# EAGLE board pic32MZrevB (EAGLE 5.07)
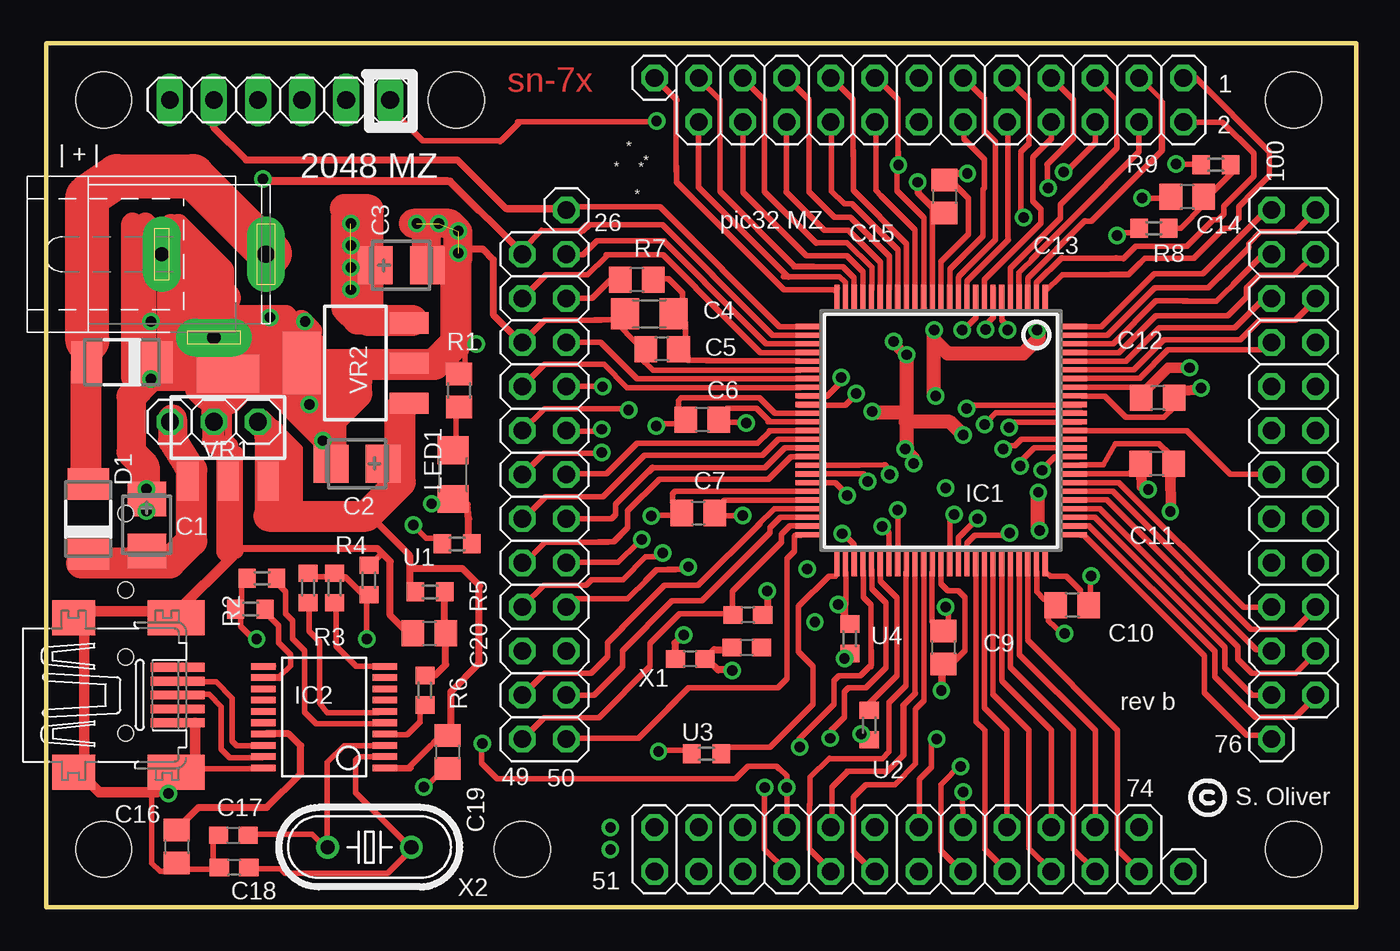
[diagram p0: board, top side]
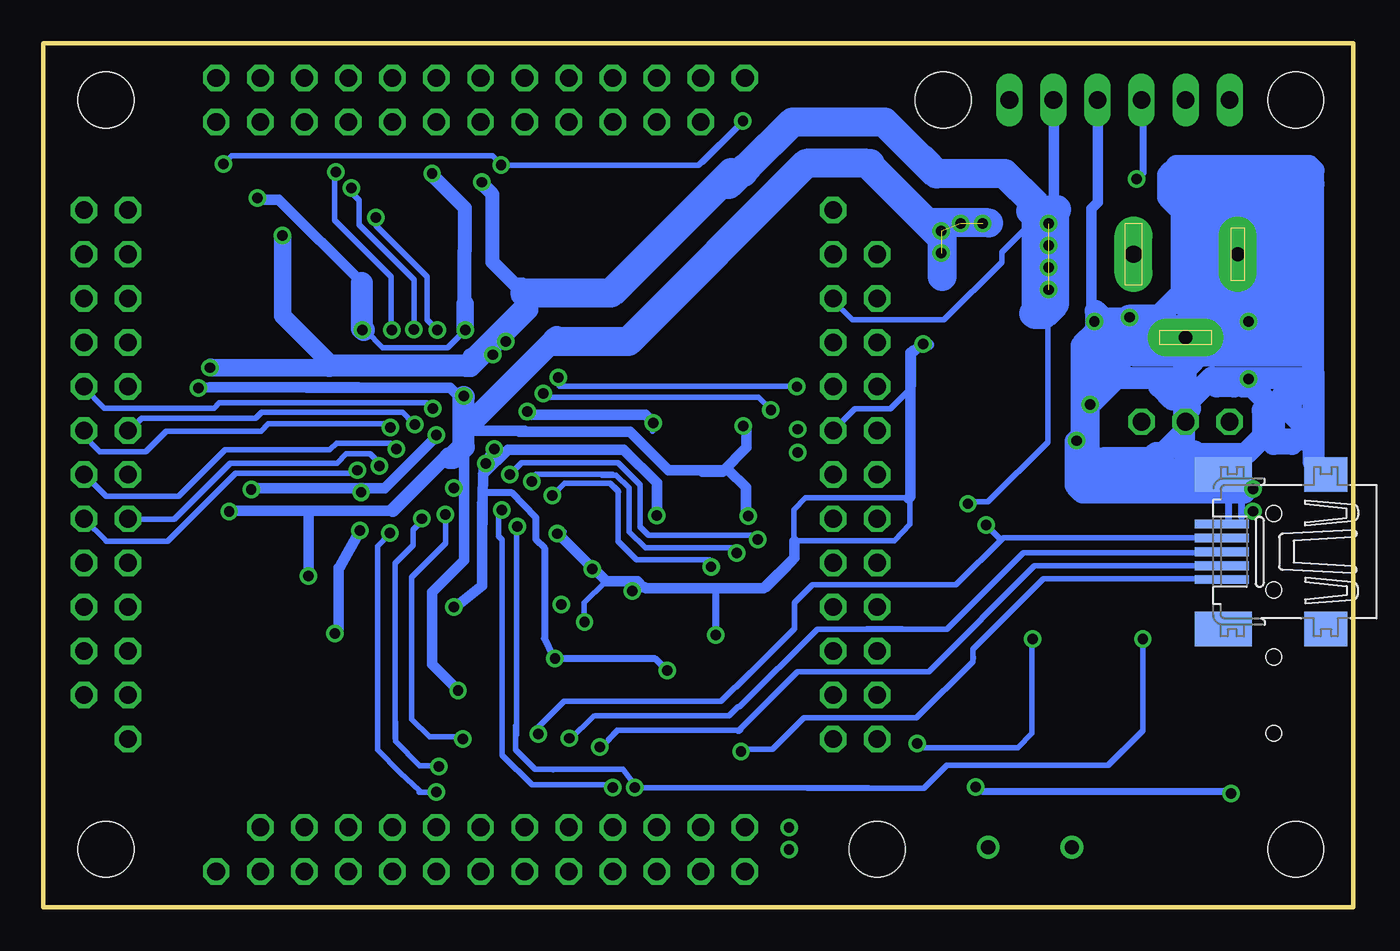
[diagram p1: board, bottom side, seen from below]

Size 75.5 x 49.78 mm. Coordinates in mm from the lower left corner, seen from the top.
Outline: 75.5,0.03 75.5,49.78 0,49.78 0,0.03
Outline: 75.5,0 0,0
Copper layers (1*16): Top 0.035mm / dielectric 1.5mm / Bottom 0.035mm
Design rules "default": minimum track width 10mil, minimum drill 24mil, track to track 8mil, track to pad 8mil, pad to pad 8mil, via to via 8mil, smd to smd 8mil, copper to edge 40mil, drill to drill 8mil, minimum pad ring 10mil, minimum via ring 8mil, stop-mask expansion 4mil, vias tented up to drill 0mil, thermal gap 10mil
Holes 3.2 mm at 3.31,46.52 3.31,3.34 71.89,3.34 71.89,46.52 23.63,46.52 27.44,3.34

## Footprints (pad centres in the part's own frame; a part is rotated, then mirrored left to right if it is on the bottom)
SPC4077 = drill 0.8 pad 2.184 long: 1 -3,0; 2 0,-4.8 | drill 1 pad 2.184 long: 3 3,0
C0805 = smd 1.3 x 1.5: 1 -0.95,0; 2 0.95,0
1X01 = drill 1.016 octagon: 1 0,0
2X12 = drill 1.016 octagon: 1 -13.97,-1.27; 2 -13.97,1.27; 3 -11.43,-1.27; 4 -11.43,1.27; 5 -8.89,-1.27; 6 -8.89,1.27; 7 -6.35,-1.27; 8 -6.35,1.27; 9 -3.81,-1.27; 10 -3.81,1.27; 11 -1.27,-1.27; 12 -1.27,1.27; 13 1.27,-1.27; 14 1.27,1.27; 15 3.81,-1.27; 16 3.81,1.27; 17 6.35,-1.27; 18 6.35,1.27; 19 8.89,-1.27; 20 8.89,1.27; 21 11.43,-1.27; 22 11.43,1.27; 23 13.97,-1.27; 24 13.97,1.27
R0603 = smd 1 x 1.1: 1 -0.85,0; 2 0.85,0
DO-214AC = smd 1.8 x 2.4: A 2.025,0; C -2.025,0
SOT223 = smd 1.219 x 2.235: 1 -2.311,-3.099; 2 0,-3.099; 3 2.311,-3.099 | smd 3.6 x 2.2: 4 0,3.099
CT3528 = smd 2 x 2.2: + -1.5,0; - 1.5,0
R0805 = smd 1.3 x 1.5: 1 -0.95,0; 2 0.95,0
C1206 = smd 1.6 x 1.8: 1 -1.4,0; 2 1.4,0
SQFP-S-14X14-100 = smd 0.3 x 1.6: 1 -6,-7.6; 2 -5.5,-7.6; 3 -5,-7.6; 4 -4.5,-7.6; 5 -4,-7.6; 6 -3.5,-7.6; 7 -3,-7.6; 8 -2.5,-7.6; 9 -2,-7.6; 10 -1.5,-7.6; 11 -1,-7.6; 12 -0.5,-7.6; 13 0,-7.6; 14 0.5,-7.6; 15 1,-7.6; 16 1.5,-7.6; 17 2,-7.6; 18 2.5,-7.6; 19 3,-7.6; 20 3.5,-7.6; 21 4,-7.6; 22 4.5,-7.6; 23 5,-7.6; 24 5.5,-7.6; 25 6,-7.6; 51 6,7.6; 52 5.5,7.6; 53 5,7.6; 54 4.5,7.6; 55 4,7.6; 56 3.5,7.6; 57 3,7.6; 58 2.5,7.6; 59 2,7.6; 60 1.5,7.6; 61 1,7.6; 62 0.5,7.6; 63 0,7.6; 64 -0.5,7.6; 65 -1,7.6; 66 -1.5,7.6; 67 -2,7.6; 68 -2.5,7.6; 69 -3,7.6; 70 -3.5,7.6; 71 -4,7.6; 72 -4.5,7.6; 73 -5,7.6; 74 -5.5,7.6; 75 -6,7.6 | smd 1.6 x 0.3: 26 7.6,-6; 27 7.6,-5.5; 28 7.6,-5; 29 7.6,-4.5; 30 7.6,-4; 31 7.6,-3.5; 32 7.6,-3; 33 7.6,-2.5; 34 7.6,-2; 35 7.6,-1.5; 36 7.6,-1; 37 7.6,-0.5; 38 7.6,0; 39 7.6,0.5; 40 7.6,1; 41 7.6,1.5; 42 7.6,2; 43 7.6,2.5; 44 7.6,3; 45 7.6,3.5; 46 7.6,4; 47 7.6,4.5; 48 7.6,5; 49 7.6,5.5; 50 7.6,6; 76 -7.6,6; 77 -7.6,5.5; 78 -7.6,5; 79 -7.6,4.5; 80 -7.6,4; 81 -7.6,3.5; 82 -7.6,3; 83 -7.6,2.5; 84 -7.6,2; 85 -7.6,1.5; 86 -7.6,1; 87 -7.6,0.5; 88 -7.6,0; 89 -7.6,-0.5; 90 -7.6,-1; 91 -7.6,-1.5; 92 -7.6,-2; 93 -7.6,-2.5; 94 -7.6,-3; 95 -7.6,-3.5; 96 -7.6,-4; 97 -7.6,-4.5; 98 -7.6,-5; 99 -7.6,-5.5; 100 -7.6,-6
C0603 = smd 1.1 x 1: 1 -0.85,0; 2 0.85,0
32005-201 = smd 3.1 x 0.5: 1 3,1.6; 2 3,0.8; 3 3,0; 4 3,-0.8; 5 3,-1.6 | smd 2.5 x 2: M1 -3,-4.45; M2 -3,4.45 | smd 3.3 x 2: M3 2.9,4.45; M4 2.9,-4.45 | hole 0.9: 0,2.2; 0,-2.2
SSOP20 = smd 0.38 x 1.4: 1 -2.925,-3.5; 2 -2.275,-3.5; 3 -1.625,-3.5; 4 -0.975,-3.5; 5 -0.325,-3.5; 6 0.325,-3.5; 7 0.975,-3.5; 8 1.625,-3.5; 9 2.275,-3.5; 10 2.925,-3.5; 11 2.925,3.5; 12 2.275,3.5; 13 1.625,3.5; 14 0.975,3.5; 15 0.325,3.5; 16 -0.325,3.5; 17 -0.975,3.5; 18 -1.625,3.5; 19 -2.275,3.5; 20 -2.925,3.5
HC49U-V = drill 0.813 round: 1 -2.413,0; 2 2.413,0
1X06 = drill 1.016 long: 1 -6.35,0; 2 -3.81,0; 3 -1.27,0; 4 1.27,0; 5 3.81,0; 6 6.35,0

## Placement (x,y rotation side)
E$1  [SPC4077]  9.66,37.63 0 top
E$2  [C0805]  64.07,29.35 180 top
E$3  [1X01]  29.98,40.17 0 top
E$4  [1X01]  35.06,47.79 0 top
E$5  [C0805]  51.77,40.97 270 top
E$6  [2X12]  51.57,46.52 0 top
E$7  [C0805]  64.02,25.57 180 top
E$8  [R0603]  63.84,39.13 180 top
E$9  [C0805]  65.77,40.94 180 top
E$10  [R0603]  67.42,42.79 0 top
E$11  [DO-214AC]  2.42,22.37 90 top
E$12  [SOT223]  17.81,31.36 90 top
E$13  [CT3528]  20.45,37 0 top
E$14  [R0805]  23.78,29.79 270 top
E$15  [C0805]  34.04,36.16 180 top
E$16  [C1206]  34.76,34.2 0 top
E$17  [C0805]  35.49,32.17 180 top
E$18  [C0805]  37.8,28.11 180 top
E$19  [SQFP-S-14X14-100]  51.57,27.47 180 top
E$20  [C0805]  59.14,17.42 180 top
E$21  [CT3528]  5.8,22.04 270 top
E$22  [SOT223]  10.47,27.65 0 top
E$23  [C0603]  37.11,14.32 180 top
E$24  [DO-214AC]  4.35,31.41 180 top
E$25  [R0603]  15.1,18.41 270 top
E$26  [R0603]  12.43,18.96 0 top
E$27  [CT3528]  17.91,25.57 180 top
E$28  [R0603]  22.13,18.18 0 top
E$29  [R0603]  23.68,20.95 0 top
E$30  [C1206]  23.45,24.93 90 top
E$31  [2X12]  28.71,23.66 90 top
E$32  [C0805]  37.57,22.72 0 top
E$33  [R0603]  47.43,10.51 90 top
E$34  [R0603]  16.62,18.41 270 top
E$35  [2X12]  71.89,26.2 90 top
E$36  [32005-201]  4.58,12.23 0 top
E$37  [SSOP20]  16.01,10.96 90 top
E$38  [R0603]  21.83,12.51 270 top
E$39  [C0805]  22.08,15.79 0 top
E$41  [R0603]  18.6,18.86 90 top
E$42  [R0603]  11.77,17.19 0 top
E$43  [C0603]  40.44,16.86 180 top
E$44  [C0603]  40.38,14.98 0 top
E$45  [C0805]  51.72,14.98 90 top
E$47  [1X01]  70.62,9.69 0 top
E$48  [C0805]  7.53,3.5 270 top
E$49  [C0603]  10.78,4.16 0 top
E$50  [C0603]  10.83,2.3 180 top
E$51  [HC49U-V]  18.63,3.47 180 top
E$52  [2X12]  49.03,3.34 0 top
E$53  [1X01]  65.54,2.07 0 top
E$55  [1X01]  7.12,27.98 0 top
E$56  [1X01]  9.66,27.98 0 top
E$57  [R0603]  38.06,8.86 180 top
E$58  [R0603]  46.31,15.49 270 top
E$59  [1X01]  12.2,27.98 0 top
E$100  [32005-201]  4.58,20.49 180 bottom
E$400  [C0805]  23.12,8.96 270 top
ICSP  [1X06]  13.47,46.52 0 top

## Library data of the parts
E$1 = con-jack
E$2 E$5 E$7-E$10 E$12-E$23 E$25-E$30 E$32-E$34 E$38 E$39 E$41-E$45 E$48-E$50 E$57 E$58 E$400 = smd-ipc
E$3 E$4 E$6 E$31 E$35 E$47 E$52 E$53 E$55 E$56 E$59 ICSP = pinhead
E$11 E$24 = diode
E$36 E$100 = con-cypressindustries
E$37 = cypress
E$51 = crystal

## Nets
S$5: E$6.16
S$22: E$52.7
S$51: E$31.15
S$61: E$35.11
S$101: E$31.4
S$259: E$6.18
S$283: E$31.2
S$476: E$52.8
S$520: E$35.9

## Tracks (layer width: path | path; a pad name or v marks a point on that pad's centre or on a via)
S$1  (via drill 0.6)
  other vias: 45.88,21.53 43.85,19.5 24.8,32.45 44.31,16.45 36.74,15.69 39.53,13.66 41.56,18.23
S$2
  Top 0.305: 50.58,35.5 50.58,39.74 49.03,41.29 49.03,42.84
S$3
  Top 0.305: 19.46,13.89 17.86,13.89 16.7,15.05 16.7,17.08
S$4
  Bottom 0.61: 51.32,29 51.47,28.85
S$5
  Top 0.305: E$6.16 56.62,46.55 56.62,43.96
S$6
  Top 0.305: 56.78,37.33 58.94,39.49 59.19,39.74 62.98,43.53 62.98,45.15
S$7  (via drill 0.6)
  other vias: 48.19,21.94
S$8
  Top 0.254: 60.44,47.79 61.68,46.55 61.68,44.01
S$9
  Top 0.305: 51.09,35.5 51.09,40.53
S$10  (via drill 0.6)
  other vias: 49.08,22.9
S$11
  Top 0.254: 62.98,45.23 63,45.2
S$12
  Bottom 0.305: 32.52,19.6 33.79,18.33 34.7,18.33 37.6,18.33
  Bottom 0.406: 43.87,19.73 43.16,18.76 41.23,18.76 40.8,18.33 34.7,18.33
S$13
  Top 0.254: 63,47.84 64.25,46.6 64.25,43.53
S$14
  Top 0.305: 27.46,17.34 28.68,18.56 31.1,18.56 31.43,18.89 33.23,18.89 34.55,20.21 35.24,20.21
S$15
  Top 0.305: 50.07,19.29 50.07,12.31 49.39,11.62 49.39,8.75 48.4,7.76
S$16
  Top 0.305: 56.88,40.68 57.34,40.23 57.34,39.41 54.09,36.16 54.09,35.73
S$17
  Bottom 0.305: 65.13,42.84 64.65,43.32 49.61,43.32 49.13,42.84
S$18
  Top 0.305: 34.68,18.94 33.51,17.77 30.51,17.77 30.03,17.29
S$19
  Top 0.305: 59.65,24.48 61.83,24.48 69.02,17.29 70.57,17.29 70.59,17.26
S$20
  Top 0.305: 51.57,35.6 51.57,37.2 53.15,38.78 53.15,40.86 52.41,41.6
S$21
  Top 0.305: 55.56,36.39 55.56,36.82 58.45,39.72 58.45,40.48 61.7,43.73 61.7,44.29
S$22
  Top 0.305: 42.68,2.05 E$52.7 41.41,3.34 41.41,6.9
S$23
  Top 0.406: 50.25,41.77 50.25,41.16 51.21,40.2
S$24
  Top 0.406: 52.18,42.31 53.17,42.31
S$25
  Top 0.305: 47.81,45.2 47.81,41.32 48.12,41.01 48.93,40.2 50.07,39.06 50.07,35.63
S$26
  Top 0.254: 60.48,45.23 60.46,45.25
S$27
  Top 0.305: 55.35,2.1 54.19,3.27
S$28
  Top 0.305: 41.13,22.11 37.58,18.56 35.64,18.56 33.13,16.04
S$29
  Bottom 0.61: 50.2,23.28 50.2,18.53 51.9,17.19
S$30
  Top 0.305: 51.06,19.32 51.06,16.48 51.14,16.4
S$31
  Top 0.305: 34.53,18.81 35.16,19.45 36.25,19.45
S$32
  Top 0.305: 52.08,35.68 52.08,36.77 53.98,38.67 53.98,41.37 54.06,41.44 54.06,43.12 52.89,44.29 52.89,45.23
S$33
  Top 0.305: 43.44,22.98 41.97,22.98 41.03,22.04
S$34
  Top 0.305: 48.57,19.37 48.57,21.58 48.22,21.94
S$35
  Bottom 0.305: 55.2,10.66 55.2,9.57 53.8,8.17 52.81,8.17 52.74,8.09
S$36  (via drill 0.6)
  other vias: 51.85,17.31
S$37
  Top 0.305: 43.42,22.47 42.32,22.47 41.72,21.86 41.72,21.58 37.8,17.67 36.08,17.67 33.23,14.83
S$39
  Bottom 0.406: 46.08,14.54 45.8,14.27
S$40
  Bottom 0.305: 35.47,9.03 35.39,9.11 33.48,9.11 31.66,10.94 25.33,10.94
S$41
  Top 1.778: 2.29,24.93 2.29,30.78
S$42
  Top 0.305: 51.57,19.35 51.57,18.66 51.98,18.25 52.56,18.25 52.94,17.87 52.94,14.8 52.13,13.99
S$43
  Top 0.305: 52,17.21 52,16.42 51.98,16.4
S$44  (via drill 0.6)
  other vias: 52.84,6.65
S$45
  Bottom 0.305: 32.06,30.04 45.75,30.04
S$46
  Top 0.305: 51.67,12.54 51.67,13.56 51.7,13.58
S$47
  Top 0.305: 59.6,17.95 59.6,18.28 58.81,19.07 57.87,19.07 57.64,19.29
S$48
  Top 0.813: 57.16,21.89 57.16,23.92
S$49
  Top 0.305: 60.18,19.22 60.18,18
S$50
  Top 0.305: 52.08,19.32 52.08,22.34 52.36,22.62
S$51
  Bottom 0.305: E$31.15 28.71,28.74 26.68,28.74 25.36,30.06 25.36,31.92 24.95,32.32 24.44,32.32
S$52
  Top 0.305: 45.14,8.6 44.03,7.48 44.03,5.91 43.98,5.86 | 45.22,2.1 43.98,3.34 43.98,5.86 | 43.98,5.86 43.98,5.91
S$53  (via drill 0.6)
  other vias: 52.71,8.12
S$54
  Top 0.406: 41.56,17.14 41.59,17.16 41.59,18.25
S$55
  Top 0.305: 59.72,30.98 62.7,30.98 64.42,32.71 68.82,32.71 69.93,33.82 71.99,33.82 73.21,35.04
S$56
  Top 0.305: 57.08,35.98 58.53,37.43
S$57
  Top 1.778: 8.39,25.19 8.39,21.12 7.12,19.85 2.04,19.85
S$58
  Top 0.305: 56.57,35.6 56.57,36.26 59.88,39.56
S$59
  Bottom 0.61: 51.42,29.3 52.05,29.94 60.31,29.94
S$60
  Top 0.305: 59.72,29.45 61.02,29.45 62.24,28.24 64.42,28.24 65.01,28.82
S$61
  Bottom 0.305: 55.25,26.48 55.51,26.74 58.61,26.74 58.99,26.36 65.03,26.36 67.7,23.69 71.86,23.69 73.11,24.93 E$35.11
S$62
  Top 0.305: 59.75,30.5 63.02,30.5 64.65,32.12 70.21,32.12 70.64,32.55
S$63
  Top 2.54: 12.89,37.69 8.44,42.13 4.07,42.13 2.37,40.94 2.37,32.66
S$64
  Top 2.54: 6.92,37.69 9.1,35.5 9.1,32.73
S$65
  Top 1.27: 13.06,27.47 13.06,22.93
S$66
  Bottom 0.305: 35.24,45.25 37.73,42.77 49.11,42.77
S$67
  Top 1.778: 12.84,22.55 18.45,22.55 20.4,24.5 20.4,28.69 20.48,28.77
S$68
  Top 1.778: 16.34,28.62 16.42,28.69 16.42,26.38
S$69
  Top 1.676: 7.27,28.13 7.27,26.89 8.14,25.52
S$70
  Top 1.778: 21.09,33.82 18.55,33.82 18.55,40.17
S$71  (via drill 0.6)
  other vias: 12.48,41.98
S$72
  Top 0.305: 58.76,33.47 60.82,33.47 63.86,36.52 66.66,36.52 70.29,40.15
S$73
  Top 0.305: 57.84,17.82 57.77,16.5 58.61,15.74 58.61,15.71
S$74
  Top 0.305: 59.75,27.47 65.74,27.47 68.26,24.96 70.54,24.96
S$75
  Top 0.305: 59.75,31.46 62.24,31.46 64.17,33.39 68.51,33.39 70.26,35.14
S$76
  Top 0.305: 57.09,19.35 57.09,18.18 57.49,17.75
S$77
  Top 0.305: 59.7,31.97 61.83,31.97 63.97,34.1 68.11,34.1 69.17,35.17 69.17,35.68 69.91,36.41 71.92,36.41 73.14,37.63
S$78
  Top 0.305: 59.75,32.48 61.5,32.48 63.97,34.94 65.74,34.94
S$79
  Top 0.305: 59.67,23.97 61.48,23.97 69.43,16.02 71.97,16.02 73.24,17.29
S$80
  Top 0.305: 59.62,29.96 62.44,29.96
S$81
  Top 0.305: 51.01,9.64 51.01,8.07 50.33,7.38 50.33,4.72
S$82  (via drill 0.6)
  Top 0.813: v52.84,27.22 52.08,27.98 49.54,27.98
S$83
  Top 0.305: 59.65,23.49 61.12,23.49 69.76,14.85 70.64,14.85 70.72,14.77
S$84
  Top 0.305: 59.65,22.98 60.74,22.98 68.69,15.03 68.69,14.29 69.48,13.5 72.02,13.5 73.29,14.77
S$85
  Bottom 0.305: 53.2,28.87 53.4,29.07 65.36,29.07 65.67,28.77 71.99,28.77 73.19,29.96
S$86
  Top 0.305: 65.54,34.92 67.44,34.92 68.84,36.31
S$87
  Top 0.305: 70.19,40.2 70.64,40.2
S$88
  Bottom 0.305: 49.26,22.72 49.26,21.38 49.05,21.17 49.05,8.78 47.33,7.05 42.96,7.05 42.88,6.98
S$89
  Bottom 1.016: 61.7,38.67 61.7,34.08 59.06,31.44
S$90
  Top 0.305: 73.21,40.15 71.99,38.93 69.98,38.93 69.3,38.24 69.3,38.02 67.57,36.29
S$91
  Bottom 0.61: 52.79,27.2 55.84,24.15 63.64,24.15 63.66,24.15
S$92
  Bottom 0.305: 33.56,28.69 34.27,29.4 42.81,29.4 45.09,29.4 46.52,29.4 46.69,29.58
S$93
  Top 0.305: 65.49,45.25 67.8,45.25 69.6,43.45 69.6,42.13 67.88,40.4 67.88,39.95 67.55,39.62 67.27,39.62 65.74,38.09 62.8,38.09 62.09,37.38
S$94
  Bottom 0.61: 57.36,29.96 65.9,29.96 66.38,29.94
S$95
  Top 0.305: 61.35,36.49 62.42,36.49 63.33,37.41 66.15,37.41 67.88,39.13 68.21,39.13 68.74,39.67 68.74,40.38 69.25,40.88
S$96
  Top 0.305: 59.75,24.98 62.42,24.98 62.59,25.16
S$97
  Top 0.305: 64.73,26.15 64.19,26.69
S$98  (via drill 0.6)
  other vias: 51.32,9.69
S$99
  Top 0.305: 49.11,43.5 49.11,42.84
S$100
  Top 0.61: 65.31,25.31 64.8,24.88 64.83,23.08
S$101
  Top 0.305: 33.23,16.17 33.23,16.15 32.34,15.26 32.34,14.44 31.4,13.5 28.71,13.5 E$31.4
S$102
  Top 0.305: 59.7,22.47 60.44,22.47 67.93,14.98 67.93,13.81 69.5,12.23 70.57,12.23 70.62,12.18
S$103
  Top 0.305: 59.72,21.99 60.1,21.99 67.34,14.75 67.34,13.3 69.68,10.96 71.99,10.96 73.26,12.23
S$104
  Top 0.305: 43.42,24.48 45.47,24.48 46.19,23.77
S$105
  Top 0.305: 43.42,24.98 47.1,24.98 47.38,24.7
S$106
  Top 0.305: 43.42,25.47 46.85,25.47 48.37,25.49
S$107
  Bottom 0.61: 55.3,22.85 64.68,22.85
S$108
  Top 0.305: 59.62,21.45 59.8,21.45 66.76,14.5 66.76,12.36 69.2,9.92 70.64,9.92 70.67,9.9
S$109
  Top 0.305: 30,19.88 32.95,19.88 34.09,21.02 34.09,21.05
S$110
  Bottom 0.406: 39.53,13.63 40.22,14.32 46.03,14.32
S$111
  Top 0.305: 43.39,23.46 39.1,23.46 38.95,23.31
S$112
  Top 0.305: 27.44,19.73 28.76,21.05 32.37,21.05
S$113
  Top 0.305: 34.93,25.37 32.8,23.23 32.8,22.62 32.57,22.39 29.93,22.39
S$114
  Top 0.305: 41.26,26.05 34.48,26.05 32.09,23.66 28.79,23.66 27.46,22.34
S$115
  Top 0.305: 29.93,24.98 32.29,24.98 34.04,26.74 41,26.74 41.74,27.47
S$116
  Top 0.305: 43.42,26.97 43.39,26.97 42.2,26.97 41.28,26.05
S$117
  Top 0.305: 32.16,26.18 28.68,26.18 27.41,24.91
S$118
  Top 0.305: 53.7,46.98 54.06,46.63 54.06,44.62
S$119  (via drill 0.6)
  other vias: 40.14,22.57
S$120
  Top 0.305: 59.65,25.52 60.92,25.52 61.63,26.71 64.12,26.71 64.78,26.05
S$121  (via drill 0.6)
  other vias: 40.34,27.91
S$122
  Top 0.305: 43.52,21.99 42.86,21.99 42.38,21.5 42.38,21.05 39.56,18.23 39.56,16.83 39.53,16.81 39.56,16.81
S$123  (via drill 0.6)
  other vias: 34.88,22.55
S$124
  Top 0.305: 39.48,14.93 39.53,14.88
S$125
  Top 0.305: 33.51,15.08 33.21,14.77 33.21,13.86 31.58,12.23 30.08,12.23
S$126  (via drill 0.6)
  other vias: 35.54,20.41 35.29,8.98 43.42,9.24 45.19,9.74 46.97,10
S$127
  Top 0.305: 41.69,27.47 43.37,27.47
S$128
  Top 0.305: 35.16,27.86 36.41,27.86
S$129  (via drill 0.6)
  other vias: 18.47,15.46
S$130
  Top 0.61: 63.51,24.15 63.15,24.22 63.13,25.01
S$131
  Top 0.61: 66,31.08 64.68,31.08 63.33,29.73 63.28,29.73 63.25,29.76
S$132  (via drill 0.6)
  other vias: 46.16,23.74
S$133
  Top 0.305: 41.72,27.98 41.59,27.98 | 41.72,27.98 43.39,27.98 | 41.72,27.98 40.93,28.77 39.23,28.77
S$134  (via drill 0.6)
  other vias: 48.62,24.93
S$135  (via drill 0.6)
  other vias: 47.35,24.53
S$136
  Top 0.305: 44.18,13 44.18,11.7 41.72,9.24 39.2,9.24
S$137
  Bottom 0.813: 51.21,34.64 51.21,37.89 51.21,37.94 51.21,40.3 53.07,42.16
S$138
  Top 0.305: 45.24,10.25 45.24,9.64 45.3,9.59
S$139
  Top 0.305: 68.16,36.85 68.13,36.85 66.99,35.7 63.89,35.7 63.84,35.65 63.71,35.53 61.15,32.96 59.7,32.96
S$140
  Bottom 1.016: 57.74,31.11 65.84,31.11 65.87,31.13
S$141  (via drill 0.6)
  other vias: 51.6,12.49 57.18,23.92 58.71,15.79 60.23,19.09 51.85,24.17
S$142
  Top 0.305: 68.41,35.91 70.14,37.63
S$143
  Top 0.305: 46.19,7.81 45.3,6.92 45.3,4.72 45.24,4.67
S$144  (via drill 0.6)
  other vias: 55.53,21.58
S$145  (via drill 0.6)
  other vias: 52.33,22.65
S$146  (via drill 0.6)
  other vias: 53.68,22.39
S$147  (via drill 0.6)
  other vias: 57.26,21.71
S$148
  Bottom 0.305: 35.31,10.2 41.46,10.2 42.38,10.2 | 42.38,10.2 42.43,10.2 42.93,9.69 | 42.38,10.2 43.37,9.21
S$149
  Bottom 0.813: 47.89,35.88 48.32,35.88 49.61,37.18 49.61,41.09 50.27,41.75
S$150
  Bottom 0.61: 60.21,22.65 60.21,19.35
S$151
  Top 0.305: 39.2,27.58 39.17,27.6 39.2,27.6
S$152
  Top 0.305: 39.28,28.72 39.25,28.69
S$153
  Top 0.305: 39.2,27.96 40.37,27.96
S$154
  Top 0.305: 43.39,28.46 41.99,28.46 41.1,29.35 36.58,29.35 36.43,29.2 36.43,28.59 36.41,28.57
S$155
  Top 0.305: 35.09,27.83 35.06,27.83
S$156
  Top 0.305: 43.42,25.97 42.93,25.97 41.64,24.68 35.34,24.68 33.51,22.85 33.51,21.89 32.7,21.07
S$157
  Top 1.778: 9.96,35.12 10.32,35.12
S$158
  Top 0.305: 43.42,26.48 42.58,26.48 41.44,25.34 34.96,25.34 34.73,25.11
S$159
  Top 0.305: 31.82,21.06 32.71,21.06 33.09,21.44
S$160
  Top 0.305: 43.42,30.95 34.96,30.95 34.15,31.77
S$161
  Top 0.305: 43.39,28.95 46.06,28.95 46.72,29.61
S$162
  Top 0.305: 27.38,27.41 28.71,28.74 33.35,28.74
S$163
  Top 0.305: 32.39,30.01 29.98,30.01
S$164
  Top 0.305: 27.44,30.01 28.71,31.28 32.14,31.28 33.47,29.95 43.44,29.95
S$165
  Top 0.305: 43.44,30.46 34.04,30.46 31.95,32.55 29.98,32.55 29.92,32.55
S$166
  Top 0.305: 43.39,29.45 44.99,29.45 45.83,30.29 45.83,30.45
S$167
  Top 0.305: 38.06,31.49 43.39,31.49
S$168
  Bottom 0.305: 42.45,18.74 43.14,18.74 44.33,17.54 44.33,16.58 44.41,16.5
S$169
  Top 0.305: 33.84,33.82 33.79,33.77 32.77,33.77 34.12,32.43 34.12,32.02
S$170
  Top 0.305: 28.56,39.01 27.44,37.89
S$171
  Top 0.305: 37.45,35.7 35.54,37.61 32.29,37.61 | 32.29,37.61 32.27,37.61 | 32.29,37.61 32.29,37.53 31.2,36.44 28.81,36.44 27.46,35.09
S$172
  Top 0.305: 29.98,37.61 30.95,37.61 31.76,38.42 35.62,38.42 35.64,38.4
S$173
  Top 0.305: 27.44,32.55 28.71,33.82 31.96,33.82
S$174
  Top 0.305: 29.98,35.09 31.45,35.09 32.62,36.26
S$175
  Top 0.305: 45.55,35.58 42.53,35.58 36.33,41.77 36.33,42.71
S$176
  Top 0.305: 37.6,45.25 37.6,44.29 37.6,43.98 37.6,41.49 42.78,36.31
S$177
  Top 0.305: 35.37,36.21 35.87,36.21 36.66,35.42 36.66,34.69
S$178  (via drill 0.6)
  other vias: 33.56,28.66
S$179
  Top 0.305: 43.44,33.47 42.25,33.47 38.92,36.8
S$180
  Top 0.305: 12.78,13.2 13.45,13.2
S$181
  Top 0.305: 43.42,32.96 41.87,32.96 38.34,36.49
S$182
  Top 0.305: 39,36.74 35.37,40.38 29.98,40.38 29.85,40.25
S$183
  Top 0.305: 37.98,36.03 35.62,38.4
S$184  (via drill 0.6)
  other vias: 37.02,19.63
S$185
  Top 0.305: 43.44,32.48 41.49,32.48 37.91,36.06
S$186
  Bottom 0.305: 42.6,24.22 42.38,23.99 42.38,21.1 41.31,20.03 37.12,20.03
S$187
  Top 0.305: 38.46,36.39 35.52,39.34 31.17,39.34 30.79,38.95 30.79,38.9
S$188  (via drill 0.6)
  other vias: 47.59,28.57
S$189
  Top 0.305: 43.39,31.97 41.16,31.97 37.42,35.7
S$190
  Top 0.305: 31.63,33.85 32.72,33.85
S$191
  Top 1.778: 16.59,28.31 17.89,29.61 17.89,30.34 17.59,30.04 16.42,30.04
S$192
  Bottom 1.676: 36,41.65 35.01,42.64 34.93,42.64 32.32,45.25 27.01,45.25 24.01,42.26
S$193  (via drill 0.6)
  other vias: 35.16,27.73
S$194  (via drill 0.6)
  other vias: 32.06,30
S$195  (via drill 0.6)
  other vias: 22.21,23.26
S$196
  Top 0.305: 38.18,31.51 36.99,31.51 36.99,31.79
S$197
  Top 0.305: 36.84,33.7 36.84,32.71
S$198
  Bottom 0.305: 37.5,42.94 35.16,45.28
S$199
  Bottom 1.676: 45.93,32.6 41.79,32.6 31.53,42.87 28,42.87 | 28,42.87 27.85,42.87 | 23.71,36.36 23.71,38.57 24.57,39.44 | 24.57,39.44 28,42.87 | 21.01,39.44 24.57,39.44
S$200
  Top 0.305: 49.08,19.29 49.08,22.88 49.03,22.93
S$201
  Top 0.305: 52.79,2.05 51.57,3.27 51.57,7.08 52.79,8.3
S$202
  Top 0.305: 45.45,35.53 45.6,35.68
S$203
  Top 0.305: 36.3,42.44 36.3,46.68
S$204  (via drill 0.6)
  other vias: 46.68,29.62
S$205
  Top 0.305: 40.14,47.77 41.41,46.5 41.41,42.51 41.41,41.34 41.41,41.24 44.38,38.27
S$206
  Top 0.305: 42.68,47.79 43.95,46.52 43.95,43.32
S$207
  Top 0.305: 45.27,47.79 46.49,46.57 46.49,43.32
S$208
  Top 0.305: 46.57,35.65 46.57,36.29 45.93,36.92 43.09,36.92
S$209
  Top 0.305: 47.07,35.65 47.07,36.62 46.16,37.56 43.82,37.56 40.16,41.21 40.16,45.2
S$210
  Top 0.305: 48.09,35.65 48.09,37.18 46.24,39.03 44.84,39.03 42.63,41.24
S$211
  Top 0.305: 42.66,41.29 42.66,45.23
S$212
  Top 0.305: 48.6,35.65 48.6,37.51 46.34,39.77 45.42,39.77 43.95,41.24 43.95,43.5
S$213
  Top 0.305: 49.08,35.65 49.08,37.89 46.44,40.53 46.01,40.53 45.27,41.27 45.27,45.2 45.22,45.25
S$214
  Top 0.305: 49.59,35.65 49.59,38.24 46.52,41.32 46.52,43.6
S$215
  Top 0.305: 37.6,47.74 38.82,46.52 38.82,41.27 43.14,36.95 44.23,36.95
S$216
  Top 0.305: 44.46,38.29 46.16,38.29 47.58,36.87 47.58,35.63
S$217  (via drill 0.6)
  other vias: 49.12,42.78 50.23,41.78 53.09,42.28
S$218
  Top 0.305: 47.76,47.79 47.86,47.79 49.08,46.57 49.08,43.04
S$219
  Top 0.305: 43.39,23.97 36.23,23.97 36.1,23.84 36.1,23.33
S$220
  Top 0.305: 39.02,22.16 39.05,22.14
S$221
  Top 0.305: 38.92,22.57 40.16,22.57
S$222
  Top 0.305: 36.23,22.6 34.86,22.6 34.83,22.62
S$223
  Bottom 0.61: 57.16,21.89 58.43,19.6
S$224
  Bottom 0.305: 48.22,9.95 48.22,21.91
S$225
  Top 0.305: 35.19,22.6 35.24,22.65
S$226
  Top 0.305: 53.58,19.32 53.58,10.71 54.11,10.2 54.11,3.34
S$227
  Top 0.305: 54.11,11.47 55.38,10.2
S$228
  Top 1.27: 5.85,30.85 5.85,30.39
  Top 1.676: 5.85,30.39 4.88,29.43 4.88,26.23 5.7,25.42 5.7,23.36
S$229
  Top 0.305: 49.56,19.32 49.56,12.77 48.57,11.78 48.57,8.96 48.19,8.58 47.81,8.58 47.58,8.58 | 47.58,8.58 47.56,8.55 | 47.58,8.58 45.14,8.58 45.09,8.53
S$230
  Top 0.305: 35.82,19.47 36.91,19.47 36.99,19.55
S$231
  Bottom 0.305: 21.9,14.42 21.9,14.37
S$232
  Top 0.305: 36.35,46.5 35.06,47.79
S$233
  Top 0.305: 46.06,35.65 46.06,36.01 45.73,36.34 42.48,36.34
S$234
  Top 0.305: 60.46,4.61 60.46,10.2 56.09,14.57 56.09,19.32
S$235
  Top 0.305: 58.02,2.05 56.65,3.4 56.65,10.2
S$236
  Top 0.305: 18.93,19.98 19.34,20.39
S$237
  Top 0.305: 54.57,19.35 54.57,12.29 56.62,10.2
S$238
  Top 0.305: 50.6,34.51 50.53,34.43
S$239  (via drill 0.6)
  other vias: 65.12,42.83
S$240
  Top 0.305: 52.61,36.36 54.72,38.47 54.72,44.11 54.11,44.72 54.13,44.72
S$241  (via drill 0.6)
  other vias: 55.42,33.28
S$242
  Top 0.305: 30,27.42 31.94,27.42 32.01,27.5
S$243
  Top 0.305: 52.81,6.54 52.84,4.79
S$244
  Top 0.305: 27.16,45.28 35.24,45.28
S$245
  Top 0.305: 56.57,19.29 56.57,15.38 61.73,10.2
S$246
  Bottom 1.676: 47.73,35.4 42.78,35.4 35.85,42.33 35.16,42.33
S$247
  Top 0.305: 55.58,13.99 55.58,19.35
S$248
  Top 1.27: 9.74,30.17 9.74,27.93 9.61,27.8 9.61,26.89 10.62,25.87
S$249
  Top 2.54: 9.61,32.43 9.91,32.73
S$250
  Top 1.27: 12.1,27.88 12.4,27.88 12.63,27.14 12.63,22.42
S$251
  Top 1.27: 14.69,33.77 15.27,33.19 15.27,32.68 15.5,32.45 15.5,30.17 14.71,29.66 14.23,30.39 6.05,30.39 5.72,30.47 5.72,39.41 | 4.96,30.47 4.96,39.41
S$252
  Top 1.27: 7.02,30.9 7.02,35.98 7.48,35.98 7.6,35.86 7.6,31.79 7.83,31.56 13.42,31.56 13.42,32.88 13.72,33.19 11.74,33.19 11.74,32.81 12.02,32.53 12.18,32.53 12.33,32.38 13.14,32.38 13.22,32.3
S$253
  Top 1.778: 16.01,31.28 22.36,31.28 23.63,32.55 23.63,37.63
S$254
  Bottom 0.305: 51.19,33.27 52.2,32.25 55.94,32.25 56.9,33.21 57.11,33.21
  Bottom 1.016: 51.19,33.27 51.19,34.79
S$255
  Bottom 0.61: 57.13,35.98 61.93,40.78 63.1,40.78
  Bottom 1.27: 57.03,33.27 57.13,33.37 57.13,35.98
S$256
  Top 0.305: 53.07,35.65 53.07,36.09 55.46,38.47
S$257
  Top 0.305: 52.59,35.7 52.59,36.26 52.61,36.34
S$258  (via drill 0.6)  (3 unrouted)
  other vias: 17.55,39.4 17.55,35.59 17.55,38.13 17.55,36.86
S$259
  Top 0.305: E$6.18 59.19,46.52 59.19,44.31 57.67,42.79
S$260
  Top 0.305: 65.56,45.36 65.59,45.33
S$261
  Top 0.305: 65.52,47.79 66.25,47.79 70.49,43.55 70.49,42.16 69.2,40.86
S$262
  Top 0.305: 52.87,47.82 52.84,47.82 53.96,46.7
S$263
  Bottom 0.61: 14.71,46.52 14.71,40.63 15.1,40.25 15.1,28.74 14.94,28.59
S$264
  Top 0.305: 55.38,4.61 55.38,10.2 54.11,11.47 54.09,11.5 54.09,13.28
S$265
  Top 0.305: 55.58,35.53 55.58,36.77
S$266
  Top 0.305: 54.09,12.26 54.09,19.29
S$267
  Top 0.305: 55.43,38.47 55.43,45.2
S$268
  Top 0.305: 63.05,37.15 62.37,36.47 58.55,36.47 57.56,35.48
S$269
  Bottom 0.305: 52.71,33.19 53.37,33.85 53.37,36.34 56.32,39.28 56.32,39.79
S$270
  Top 0.305: 64.32,46.4 64.32,43.63 62.34,41.65 61.7,41.01 60.23,39.54 59.88,39.54
S$271  (via drill 0.6)
  other vias: 52.8,33.28
S$272  (via drill 0.6)
  other vias: 63.17,40.87
S$273
  Top 0.305: 59.19,3.34 60.41,2.18 | 59.19,3.34 59.22,3.37 | 59.19,3.34 59.19,10.2 55.58,13.83 55.58,14.5
S$274  (via drill 0.6)
  other vias: 58.64,42.37
S$275
  Top 0.305: 62.98,2.1 61.78,3.29
S$276
  Top 0.305: 11.26,18.58 11.26,17.42 11.11,17.26
S$277
  Top 0.305: 58.17,43.27 57.69,42.79 57.69,41.44
S$278
  Top 0.305: 55.08,19.29 55.08,13.05 57.92,10.2 57.92,4.61
S$279
  Top 0.254: 57.92,45.1 57.97,45.15 57.92,45.2
  Top 0.305: 57.92,45.2 57.92,44.29 56.85,43.22 56.85,40.73
S$280
  Top 0.305: 61.73,3.34 61.73,10.2
S$281
  Bottom 0.305: 12.1,42.31 12.56,41.85
  Bottom 0.406: 12.1,42.31 12.1,46.35
S$282
  Top 0.305: 30.11,40.23 30.08,40.2 30,40.2 26.6,40.2 24.04,42.77
  Top 0.406: 9.66,46.47 9.66,44.92 11.51,43.07 23.68,43.07 26.48,40.28 29.93,40.28 30,40.2
S$283
  Top 0.305: E$31.2 28.68,10.94 31.86,10.94 34.81,13.89 34.81,15.21 36.51,16.91 39.3,16.91
S$284
  Top 0.406: 12.48,41.85 23.27,41.85 27.44,37.69
S$285  (via drill 0.6)
  other vias: 65.91,31.09
S$286
  Top 0.305: 29.98,9.75 34.15,9.75 36.33,11.93
S$287
  Bottom 0.61: 51.24,26.33 51.24,20.01 53.09,18.15 53.09,14.01 51.59,12.51
S$288
  Bottom 0.61: 58.48,19.57 58.48,16.04 58.73,15.79
S$289
  Bottom 0.305: 26.02,16.04 28.02,16.04
S$290
  Bottom 0.305: 54.21,27.93 54.8,28.52 62.92,28.52 63.25,28.18 69.83,28.18 70.47,27.55 70.67,27.55
S$291
  Top 0.305: 58.68,42.28 60.46,44.06 60.46,45.33
S$292
  Top 0.305: 56.62,43.93 56.57,43.93 56.17,43.53 56.17,39.77 56.27,39.67
S$293
  Bottom 0.305: 55.71,27.73 55.84,27.86 62.54,27.86 62.95,27.45 68.41,27.45 69.6,26.25 72.25,26.25 73.21,27.22 73.21,27.42
S$294
  Top 0.305: 52.59,19.32 52.59,21.3 53.65,22.37
S$295  (via drill 0.6)
  other vias: 54.15,33.3
S$296
  Top 0.305: 53.07,19.37 53.07,20.97 53.53,21.43 55.38,21.43 55.51,21.56
S$297  (via drill 0.6)
  other vias: 61.72,38.72
S$298  (via drill 0.6)
  other vias: 57.12,33.28
S$299
  Bottom 0.305: 55.53,21.53 56.24,20.82 56.24,9.08 54.92,7.76 53.86,6.75
S$300
  Top 0.305: 48.32,25.49 48.62,25.19 48.62,24.81
S$301
  Bottom 0.305: 53.63,22.32 54.19,21.76 54.19,20.87 55.23,19.83 55.23,9.75
S$302
  Bottom 0.305: 56.22,25.67 56.67,26.13 58.05,26.13 58.58,25.59 64.73,25.59 67.95,22.37 70.62,22.37
S$303  (via drill 0.6)
  other vias: 55.15,26.41
S$304  (via drill 0.6)
  other vias: 57.41,25.19
S$305
  Bottom 0.305: 57.54,25.21 57.74,25.01 64.42,25.01 68.33,21.1 71.89,21.1
S$306  (via drill 0.6)
  other vias: 64.79,22.81
S$307  (via drill 0.6)
  other vias: 55.49,27.64
S$308  (via drill 0.6)
  other vias: 63.52,24.08
S$309  (via drill 0.6)
  other vias: 54.1,27.82
S$310
  Top 0.305: 59.7,26.97 56.19,26.97 55.84,26.61 55.2,26.61 55.2,26.66
S$311
  Top 0.305: 59.7,26.48 56.95,26.48 56.04,25.57
S$312
  Top 0.305: 59.7,25.97 58.12,25.97 57.49,25.34
S$313
  Top 0.305: 59.65,28.95 53.25,28.95 53.15,28.85
S$314
  Top 0.305: 59.7,28.49 54.74,28.49 54.19,27.93
S$315
  Top 0.305: 59.65,27.96 55.74,27.96 55.51,27.73
S$316
  Bottom 0.305: 52.28,22.62 52.31,22.6 52.31,20.97 54.26,19.02 54.26,10.84 53.25,9.82 51.34,9.82 51.32,9.85
S$317  (via drill 0.6)
  other vias: 66.57,29.93 53.06,28.76
S$318
  Bottom 1.016: 47.48,35.27 47.48,34.41 50.83,31.05 50.83,31.72 50.76,31.72 47.81,34.66
S$319
  Bottom 0.305: 43.95,19.6 45.98,21.63 45.47,21.63
S$320
  Top 0.305: 46.57,19.42 46.57,20.92 45.96,21.53
S$321
  Top 0.305: 45.47,19.09 45.12,19.09 43.37,17.34 43.37,14.72 44.2,13.89 44.2,11.75
S$322
  Bottom 0.406: 49.89,23.92 48.52,23.92 47.12,22.47 47.12,21.23 46.62,20.72 46.62,15.49 46.13,14.44
S$323
  Top 0.305: 46.08,19.27 46.08,17.9 46.06,16.86 45.55,17.39
S$324
  Top 0.305: 12.84,16.78 13.39,16.22 13.39,15.26 14.08,14.57 14.08,13.94 13.42,13.28 12.91,13.28
S$325
  Bottom 0.305: 25.56,23.64 25.56,22.06 26.45,21.12 32.04,21.12 32.32,20.89
  Bottom 0.61: 24.44,32.43 24.93,32.43 25.28,32.07 25.38,32.07 25.51,31.94 25.51,23.69 25.56,23.64 25.64,23.56
S$326
  Bottom 0.305: 25.59,23.61 31.58,23.61 32.24,22.9 32.24,19.9 32.72,19.42
S$327
  Bottom 0.61: 32.22,21.1 32.22,20.16 33.99,18.38 40.77,18.38 40.85,18.46 40.93,18.46 41.26,18.79 43.04,18.79 43.75,19.5
S$328
  Top 0.61: 65.18,29.76 66.66,29.84
S$329
  Top 0.305: 65.11,42.82 66.28,42.82
S$330
  Top 0.305: 67.09,41.01 67.09,41.09 68.51,42.51
S$331
  Top 0.305: 63.2,40.86 64.37,40.86
S$332
  Top 0.305: 62.75,38.88 61.71,38.87
S$333
  Top 0.305: 66.73,40.48 65.39,39.13 64.8,39.13
S$334
  Top 0.305: 53.58,35.68 53.58,33.98 53.07,33.47 52.84,33.47
S$335
  Top 0.305: 54.59,35.68 54.59,34 53.96,33.37
S$336
  Top 0.305: 55.08,35.68 55.08,33.82 55.56,33.34
S$337
  Bottom 0.61: 43.82,19.6 43.9,19.6 45.85,21.56
S$338
  Bottom 0.305: 57.79,41.24 57.31,40.76 57.31,39.34 54.13,36.16 54.13,33.27
S$339
  Bottom 0.305: 58.71,42.31 58.71,39.59 55.46,36.34 55.46,33.34
S$340
  Bottom 0.406: 36.74,15.74 36.74,18.2 36.76,18.23
S$341
  Top 0.406: 39.45,13.68 38.72,13.68 38.23,14.16 38.23,14.6 38.49,14.85 39.3,14.85
S$342
  Top 0.305: 56.07,35.65 56.07,36.57 57.06,37.56
S$343
  Bottom 0.305: 34.76,13.56 36.43,11.88 45.5,11.88 47,10.38 47,10.1
S$344
  Bottom 0.305: 8.7,19.68 18.37,19.68 24.47,13.58 32.04,13.58 35.47,10.15 35.42,10.15 35.39,10.18
S$345
  Bottom 0.305: 45.2,9.62 43.8,11.02
S$346
  Top 0.305: 13.47,18.51 13.8,18.18 13.8,16.93 14.21,16.53 14.21,15.49 14.89,14.8 14.89,11.24 15.55,10.58 19.46,10.58
S$347
  Bottom 0.305: 8.62,18.94 17.86,18.94 21.93,14.88 21.93,14.16 25.18,10.91 25.84,10.91
S$348
  Top 0.305: 57.08,35.48 57.08,35.86
S$349
  Top 0.305: 61.68,37.43 61.65,37.43
S$350
  Bottom 0.305: 48.27,10.46 48.27,9.08 47.15,7.97 46.11,7.97 | 46.11,7.97 46.11,7.94 | 46.11,7.97 42.1,7.97 41.33,6.95 41.33,6.98
S$353
  Top 0.305: 15.15,17.19 15.15,15.92 15.76,15.31 15.76,11.75 16.19,11.22 19.13,11.22 19.18,11.27
S$354
  Top 0.305: 35.26,9.06 37.02,9.06
S$355
  Top 0.305: 48.09,19.32 48.09,18.79 49.03,17.85 49.03,13.35 47.35,11.68
S$356
  Top 0.305: 50.1,12.34 49.44,11.68 49.44,8.81 48.47,7.84 47.12,7.84 46.87,7.84 46.16,7.84
S$357
  Top 0.305: 11.21,16.91 11.21,16.2 12.05,15.36
S$358
  Top 0.305: 47.1,19.37 47.1,17.87 47.53,17.44 47.53,13.86
S$359
  Top 0.305: 19.26,20.39 19.26,20.41
S$360
  Top 0.305: 47.58,19.42 47.58,18.36 48.4,17.54 48.4,13.81 47.25,12.67 46.24,12.67 46.01,12.44 46.01,10.96 45.22,10.18 45.22,9.67
S$361
  Bottom 0.305: 8.62,20.44 19.01,20.44 23.43,16.02 30.89,16.02 35.37,11.55 35.47,11.55 35.97,11.04 43.67,11.04
S$362
  Top 0.305: 57.08,35.88 57.08,35.25
S$363
  Top 0.305: 57.06,35.98 57.06,35.58
S$364
  Top 0.305: 58.66,37.41 62.14,37.41
S$365
  Top 0.305: 51.57,13.25 51.57,12.74
S$366
  Top 0.305: 15.5,19.04 17.23,19.04 18.27,18
S$367
  Top 0.305: 18.47,15.49 18.47,17.82 18.52,17.87
S$368
  Top 1.27: 7.17,39.31 7.6,39.31 10.19,36.72 10.19,35.55 10.35,35.4
S$369
  Bottom 0.305: 52.92,6.65 53.83,6.65 53.86,6.67
S$370
  Bottom 1.27: 50.78,31.39 50.73,31.39
S$371
  Bottom 1.27: 51.11,31.21 59.01,31.21
S$372
  Top 0.305: 47.56,14.77 47.56,13.99 46.92,13.35 45.7,13.35 45.4,13.05 45.4,11.7 43.42,9.72 | 43.42,9.72 43.42,9.75 | 43.42,9.72 43.42,9.26 43.34,9.19
S$373
  Top 0.305: 47.68,2.05 46.52,3.22 46.52,6.34 47.25,7.08 48.9,7.08 50.1,8.27 50.1,11.42 50.58,11.9 50.58,13.33 50.58,13.35 50.58,19.45
S$375
  Top 1.27: 8.64,30.01 8.64,29.79 9.08,29.35 9.3,29.35 9.61,29.05
S$376
  Top 1.27: 10.12,29.05 10.62,29.05 11.59,30.01
S$377
  Top 1.27: 12.76,30.09 12.84,30.09 16.01,26.91
S$378
  Bottom 1.27: 8.26,25.14 8.26,25.37 9.15,26.25 9.66,26.25 9.74,26.18 9.74,27.37 | 9.61,32.73 9.74,32.6 9.74,27.37 | 9.74,27.37 10.93,26.18 11.36,26.18 11.67,25.87 14.46,25.87
S$379
  Bottom 0.406: 6.43,22.5 6.43,24.04
S$380
  Bottom 1.27: 2.37,40.63 9.81,40.63 9.89,40.71
S$381
  Bottom 1.27: 2.67,39.54 9.3,39.54 9.53,39.77
S$382
  Bottom 1.27: 2.75,38.57 9.3,38.57 9.46,38.42
S$383
  Bottom 1.27: 2.67,37.61 9.51,37.61 9.74,37.84
S$384
  Bottom 1.27: 2.95,36.59 9.1,36.59 9.3,36.8
S$385
  Bottom 1.27: 2.45,35.63 9.38,35.63 9.53,35.78
S$386
  Bottom 1.27: 2.67,34.51 9.58,34.51 9.74,34.66
S$387
  Bottom 1.27: 2.88,33.49 12.68,33.49 12.84,33.34
S$388
  Bottom 1.27: 3.03,32.68 12.33,32.68 12.63,32.38
S$389
  Bottom 1.27: 2.88,31.79 12.61,31.79 12.68,31.87
S$390
  Bottom 1.27: 6.36,30.01 5.85,30.01 4.58,28.74 4.58,26.97 2.29,26.97 | 9.41,28.74 9.41,29.25 8.14,30.52 2.55,30.52 2.29,30.78 | 2.29,30.78 2.29,41.67 | 2.29,41.67 2.29,42.46 2.55,42.71 10.17,42.71 10.68,42.21 10.68,40.94 9.91,40.17 9.91,35.35 11.18,34.08 12.96,34.08 13.47,33.57 13.47,30.52 9.91,30.52 9.66,30.27 9.66,31.03 9.15,31.54 | 2.29,41.67 9.81,41.67 | 2.29,30.78 2.29,27.22 | 2.29,26.97 2.29,25.7 | 2.29,26.97 2.29,27.22 | 2.29,27.22 3.56,28.49 3.56,29.25 3.31,29.51 4.07,29.51
S$391  (via drill 0.6)
  other vias: 56.33,39.75
S$392
  Bottom 1.27: 6.87,30.01 7.88,30.01 7.88,30.27
S$393  (via drill 0.6)
  other vias: 51.18,33.28
S$394  (via drill 0.6)
  other vias: 57.75,41.46
S$395
  Bottom 1.27: 11.18,30.01 10.42,29.25
S$396
  Top 0.305: 20.96,7.99 20.58,7.99
S$397
  Top 0.305: 21.55,10.66 21.55,11.9 21.57,11.93
S$398
  Top 0.305: 21.5,10.63 20.81,9.95 19.9,9.95
S$399
  Top 0.305: 21.01,8.04 19.9,8.04
S$400
  Top 0.305: 19.08,8.68 18.02,8.68 17.84,8.5 17.84,6.59 21.01,3.42
S$401
  Top 0.305: 19.16,9.31 17.15,9.31 16.19,8.35 16.19,3.42
S$402
  Top 0.305: 11.92,4.21 15.32,4.21 16.11,3.42
S$403
  Top 0.305: 12,2.23 13.49,2.23 13.75,1.97 19.67,1.97 21.01,3.32
S$404
  Top 0.305: 9.61,3.95 9.61,2.35 9.46,2.2 7.86,2.2 7.73,2.07 6.56,2.07 6.08,2.56 6.08,7.13 6.23,7.28
S$405
  Top 0.305: 8.41,7.99 12,7.99
S$406
  Top 0.406: 12.63,10 13.98,10 14.66,9.31 14.66,7.71 12.71,5.76 8.77,5.76 7.86,4.84
S$407
  Top 0.305: 8.64,8.12 8.59,8.17
  Top 0.61: 8.59,8.17 8.59,10.63
S$408
  Top 0.305: 8.72,12.29 9.38,12.29 10.09,11.57 10.09,9.11 10.57,8.63 12.43,8.63
S$409
  Top 0.305: 12.61,9.31 10.98,9.31 10.73,9.57 10.73,12.06 | 10.73,12.06 9.79,13 | 9.79,13 8.72,13 8.64,13.07 | 10.73,12.06 9.79,13
S$410
  Top 0.406: 18.52,20.67 19.08,20.67 19.82,19.93 19.82,16.83 20.73,15.92
S$411
  Top 0.406: 21.8,13.4 22.44,13.4 23.02,13.99 23.02,15.66
S$412
  Top 0.305: 23.3,18.13 23.12,18.3
S$413
  Top 0.406: 22.94,15.92 22.94,18.18 22.89,18.23
S$414
  Top 0.305: 13.11,13.89 12.61,13.89
S$415
  Top 0.305: 21.62,8.81 23,10.18
S$416
  Top 0.305: 19.64,7.99 20.84,7.99 22.16,9.31
S$417
  Bottom 1.27: 8.8,25.21 14.38,25.21
S$418
  Bottom 1.27: 8.72,24.4 14,24.4 14.31,24.7
S$419
  Top 0.406: 11.11,20.69 19.08,20.69
S$420
  Bottom 1.27: 13.06,33.93 14.41,33.93 14.84,34.36 14.84,33.19 15.65,32.38 15.65,27.2 16.01,26.84 16.01,24.32 15.6,23.92 6.26,23.92 6.28,24.4
S$421
  Bottom 1.27: 15.27,28.82 15.27,25.29 15.12,25.14
S$422
  Bottom 1.27: 13.8,30.45 13.8,30.37 15.04,29.12
S$423
  Top 0.406: 21.07,19.52 23.99,19.52 24.95,18.56 | 24.95,18.56 25,18.51 | 24.95,18.56 24.95,14.06 23.32,12.44 23.32,10.35 23.38,10.3
S$424
  Top 0.305: 21.75,6.82 22.49,7.56 22.72,7.56
S$425
  Bottom 0.305: 14.13,8.2 14.11,8.2 12.12,10.18 12.12,15.31 | 31.45,6.88 24.75,6.88 23.43,8.2 14.13,8.2 | 14.13,8.2 13.27,9.06
S$426
  Bottom 0.305: 18.55,15.38 18.52,15.36 18.52,10.02 19.34,9.21 25.18,9.21
S$427
  Top 0.305: 2.19,17.14 2.27,17.06 | 6.36,6.65 6.92,7.21 | 10.96,20.51 10.73,20.74
  Top 0.61: 10.45,20.51 10.7,20.21 7.55,17.06 2.27,17.06 | 2.19,17.14 2.19,7.51 3.06,6.65 6.36,6.65
  Top 0.813: 10.45,20.51 10.96,20.51 10.96,26.18
  Top 1.27: 10.45,20.51 10.45,26.56
S$428
  Bottom 1.27: 14.54,33.11 14.54,30.98 14.23,30.67
S$429
  Bottom 0.406: 7.17,22.27 7.17,23.82
S$430
  Bottom 0.61: 17.25,46.45 17.25,39.49 17.18,39.41
S$431
  Bottom 0.305: 17.28,45.94 17.48,46.14
S$432
  Top 0.305: 31.27,39.28 30.97,38.98 28.61,38.98
S$433
  Top 0.305: 24.88,40.15 23.1,41.93 12.45,41.93
S$434
  Top 1.676: 18.5,33.85 17.94,33.85 17.25,34.53 17.25,39.89 17.43,40.07
S$435
  Top 0.406: 10.47,28.79 10.47,26.56 10.45,26.53
S$436
  Top 0.305: 19.84,46.52 19.84,46.02 21.7,44.16 26.2,44.16 | 26.2,44.16 26.14,44.11 | 27.29,45.25 26.22,44.19 26.2,44.16
S$437
  Bottom 1.676: 18.42,34.23 18.27,34.38 18.27,40.45 20.1,42.28 21.73,42.28 21.95,42.28 23.99,42.28 24.8,43.09
S$438
  Top 0.305: 19.64,46.27 19.57,46.27
S$439
  Top 1.676: 21.17,39.41 23.22,39.41 23.73,38.9 23.73,37.38 23.71,37.35 21.95,37.35 21.93,37.33 21.93,39.21 22.08,39.36
S$440
  Bottom 1.676: 18.35,34.15 17.84,34.15 17.2,34.79 17.2,39.92 17.36,40.07
S$441
  Bottom 1.676: 17.1,40.2 18.52,40.2 18.6,40.12
S$442
  Top 1.676: 17.18,40.28 18.47,40.28 18.52,40.23
S$443
  Top 0.305: 23.66,41.44 27.24,37.86
S$444
  Top 0.305: 23.63,26.2 23.63,28.74
S$445
  Top 0.406: 22.16,23.21 24.27,23.21 24.34,22.37 24.34,21.3
S$446
  Bottom 0.305: 17.59,27.37 17.59,35.55
S$447
  Top 0.406: 11.44,29.51 12.96,29.51
S$448
  Top 0.305: 23.63,31.28 24.09,31.28 24.14,31.33 24.14,31.97 24.19,32.02
S$449  (via drill 0.6)
  other vias: 45.82,30.53
S$450
  Top 0.406: 9.15,27.98 9.15,28.74 8.9,29
S$451
  Top 1.27: 13.8,34.08 10.75,34.08 10.47,34.36 10.47,34.43
S$452
  Top 0.61: 14.49,22.7 14.49,26.43 12.58,28.34 12.58,27.58 13.93,26.23 13.93,23.56 13.88,23.51
S$453
  Top 1.27: 15.48,29.2 15.43,27.73
S$454
  Top 0.406: 36.71,15.61 36.61,15.61 36.23,15.23 36.23,14.5
S$455
  Bottom 0.305: 34.86,22.62 34.81,22.57
S$456
  Bottom 1.27: 6.64,24.78 6.64,25.42
S$457
  Bottom 0.305: 48.67,24.88 47.94,25.62 42.38,25.62 41.1,24.35 41.1,21.94 40.62,21.45 34.22,21.45
S$458
  Top 0.305: 43.49,21.45 43.19,21.45 43.11,21.38 43.11,20.51 42.68,20.08 42.68,13.17 42.17,12.67 37.02,12.67 35.82,11.47
S$459
  Bottom 0.305: 47.4,24.65 47.1,24.96 42.68,24.96
S$460
  Bottom 0.305: 43.29,24.91 42.48,24.91 41.74,24.17 41.74,21.66 40.8,20.72 35.52,20.72
S$461
  Bottom 1.27: 5.21,28.64 5.21,27.12 6.23,26.1 9.05,26.1 9.13,26.18
S$462
  Bottom 0.305: 46.16,23.71 45.45,24.43 42.83,24.43 42.35,23.94
S$463
  Bottom 1.27: 3.51,26.71 4.58,26.71
S$464
  Bottom 1.27: 51.27,29.4 51.27,26.53 51.9,25.9 52.08,25.9
S$465
  Bottom 0.813: 55.35,22.9 52.2,26.05
S$466
  Top 0.61: 48.78,32.55 49.54,31.79
S$467
  Bottom 0.305: 18.98,39.06 18.98,39.01 20.25,37.74 20.25,37.18 23.58,33.85 28.86,33.85 30.03,35.02
S$468
  Bottom 0.61: 40.32,27.91 40.8,28.39 47.73,28.39
S$469
  Bottom 0.61: 40.14,22.39 40.14,24.48 42.05,26.38 48.73,26.38 50.12,24.98 50.12,25.44 50.17,23.87 50.17,22.14
S$470
  Bottom 0.61: 48.04,27.4 41.69,27.4 39.48,25.19 36,25.19 35.01,24.2 35.01,22.57 34.93,22.5
S$471
  Bottom 0.305: 40.39,27.45 40.39,27.96
S$472
  Bottom 0.61: 37.5,25.11 36.35,25.11 34.96,26.51 34.96,27.65 35.16,27.86
S$473
  Top 0.813: 49.61,31.77 49.61,26.43 49.54,26.36
S$474
  Bottom 0.61: 47.76,27.47 51.06,27.47
S$475
  Top 0.61: 50.05,25.44 50.05,25.95 49.54,26.46
S$476
  Top 0.305: E$52.8 42.68,7.59 42.27,7.99 42.22,7.99 42.1,8.12 40.45,8.12 39.73,7.41 25.99,7.41 25.1,8.3 25.1,9.42
S$487
  Bottom 1.016: 51.24,27.35 51.24,27.78
S$488
  Bottom 1.27: 46.03,32.63 45.91,32.86 51.14,27.63
S$491
  Top 0.813: 47.63,28.52 49.51,28.52 49.54,28.54
S$492
  Bottom 0.61: 49.59,26.33 50.1,25.49 49.72,25.62
S$493
  Top 0.61: 51.24,29.38 51.16,29.45
  Top 0.813: 51.16,29.45 51.16,32.71 | 51.16,32.71 51.16,33.21 | 51.16,32.71 51.95,31.92 56.32,31.92 57.21,32.81 57.21,33.27
S$497  (via drill 0.6)
  other vias: 34.32,21.2 46.01,14.34 45.65,17.44
S$499  (via drill 0.6)
  other vias: 32.01,26.2 32.01,27.55
S$500  (via drill 0.6)
  other vias: 15.17,28.97
S$501  (via drill 0.6)
  other vias: 12.12,15.46
S$502  (via drill 0.6)
  other vias: 5.77,24.1 5.77,22.83 12.89,34 6.03,33.75 15.93,26.89 6.03,30.45 14.92,33.75
S$503  (via drill 0.6)
  other vias: 7.04,6.57
S$505  (via drill 0.6)
  other vias: 21.75,6.93
S$506  (via drill 0.6)
  other vias: 35.17,45.32
S$507  (via drill 0.6)  (3 unrouted)
  other vias: 23.74,37.7 23.74,37.7 23.74,38.97 22.63,39.4 21.36,39.4
S$508  (via drill 0.6)
  other vias: 49.6,31.84 48.84,32.6 50.01,25.57
S$510  (via drill 0.6)
  other vias: 42.68,6.9
S$511
  Bottom 0.305: 8.54,21.3 20.18,21.3 22.89,18.58 31.17,18.58 32.22,17.54 32.22,16.04 35.52,12.74 35.52,12.72
S$518
  Bottom 0.406: 6.97,6.59 7.04,6.67 21.37,6.67 21.6,6.9 21.85,6.9
S$520
  Bottom 0.305: 71.89,21.12 E$35.9
S$523  (via drill 0.6)
  Bottom 0.305: 27.95,6.9 v41.41,6.9
S$524
  Top 0.305: 22.46,21.28 21.9,21.28 21.17,22.01
S$530  (via drill 0.6)
  other vias: 51.25,29.46
S$531  (via drill 0.6)
  other vias: 49.5,26.41
S$532
  Bottom 0.305: 20.4,21.28 21.09,21.96 21.09,22.04
S$533
  Top 0.406: 19.03,22.19 20.96,20.26 20.96,17.87
S$534
  Bottom 0.305: 17.61,29.56 17.61,26.81 21.07,23.36 22.21,23.36 22.23,23.33
S$537  (via drill 0.6)
  other vias: 25.13,9.44
S$538  (via drill 0.6)
  other vias: 32.52,4.61
S$539  (via drill 0.6)
  other vias: 56.14,25.44
S$540  (via drill 0.6)
  other vias: 32.52,3.34
S$541  (via drill 0.6)
  other vias: 21.17,22.04
S$543
  Top 0.406: 24.34,37.94 25.15,37.94 25.76,37.33 25.76,34.15 27.52,32.4

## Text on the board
Top: sn-7x
tNames: 1 | 2 | * | | + | | * | * | * | R9 | 2048 MZ | 100 | * | pic32 MZ | C3 | 26 | C15 | C13 | C14 | R7 | R8 | C4 | R1 | VR2 | C5 | C12 | C6 | VR1 | C7 | D1 | IC1 | LED1 | C2 | C1 | R4 | U1 | C11 | R5 | R2 | U4 | R3 | C10 | C9 | R6 | C20 | IC2 | X1 | rev b | U3 | U2 | 76 | 49 | 50 | 74 | C17 | S. Oliver | C16 | C19 | C18 | X2 | 51
tStop: sn-7x
Document: sn-5+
